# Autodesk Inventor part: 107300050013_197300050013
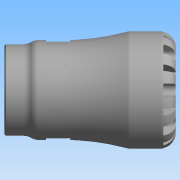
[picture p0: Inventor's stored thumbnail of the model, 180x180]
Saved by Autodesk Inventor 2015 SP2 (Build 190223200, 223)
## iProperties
Created: 2016-12
Part Number: 107300050013_197300050013
Material: Generic
Description: PLASSON FEMALE INTEGRAL BRASS THREAD 50-1.1/4" SERIES 1
Document SubType Name: Modeling
Designer: KIM
Density: 1 g/cm^3
Appearance: Default
Author: KIM
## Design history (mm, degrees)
derived "1073.ipt"
feature "Solid1::1073.ipt"
tag "TaggingFeature1"
body "Solid1"
other parameters: "d0" = 124, "d1" = 34.02, "d3" = 62.5, "d4" = 85, "d6" = 81, "d8" = 72.25, "d13" = 9, "d14" = 9, "d15" = 0, "d17" = 360 deg, "d19" = 8 deg, "d20" = 1, "d21" = 1, "d22" = 8 deg, "d24" = 0, "d26" = 360 deg, "d32" = 8.5, "d33" = 8.5, "d39" = 1.16856, "d42" = 38.952, "d43" = 66.3, "d46" = 4.16667, "d47" = 21, "d48" = 37.0044, "d50" = 7.26, "d51" = 0.85, "d54" = 17.5, "d55" = 11, "d57" = 17.64, "d58" = 0, "d68" = 360 deg, "d72" = 1, "d74" = 0, "d76" = 14.875, "E_" = 85, "H_" = 124, "l_" = 81, "G_" = 38.952, "l_2" = 21, "d9" = 11.25, "d11" = 85, "d12" = 62.5, "d49" = 22
